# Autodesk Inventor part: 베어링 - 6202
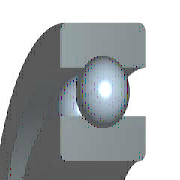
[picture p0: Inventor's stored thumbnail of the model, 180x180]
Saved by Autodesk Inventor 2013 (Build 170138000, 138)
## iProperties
IsCustomPart: 1
Created: 2015-09
Part Number: 베어링 - 6202
Material: 강, 연강
Description: 깊은 그루브 볼 베어링
Document SubType Name: Modeling
Standard: KS B 2023
Designer: mduedu
Standards Organization: KS
Language: ko-KR
Size Designation: 6202 - 15 x 35 x 11
Categories: <MemberInstance><Categories><Category DisplayName="샤프트 부품" InternalName="7f7aeb1f-a693-4053-b835-cee3144e0d98" Mnemonic="SHFT"><Category DisplayName="베어링" Inter
Density: 7.86 g/cm^3
Mass: 45.8725 g
Surface Area: 51.5584 cm^2
Volume: 5.83619 cm^3
Author: mduedu
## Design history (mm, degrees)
sketch "스케치" dims "d0" = 5.2 (= -0.26 x WD + 0.26 x BD)
  geometry: L1 (2.9, 12.5)-(8.1, 12.5); L2 (5.5, 12.5)-(5.5, 9.9); L3 (5.5, 12.5)-(5.5, 15.1); L4 (3.568, 10.76)-(0, 10.76); L5 (0, 7.5)-(11, 7.5); L6 (3.568, 14.24)-(0, 14.24); L7 (0, 17.5)-(11, 17.5); L8 (11, 7.5)-(11, 10.76); L9 (7.432, 10.76)-(11, 10.76); L10 (7.432, 14.24)-(11, 14.24); L11 (11, 17.5)-(11, 14.24); L12 (-1.4, 0)-(8.4, 0) reference; L13 (0, -0.3)-(0, 5.3) reference
  constraints: 22 end point, 4 point on line, 2 collinear, 2 perpendicular, 2 symmetric about line, 1 midpoint, 1 parallel, 14 other
  dimensions: "d9" = 15 diameter of L5 L12 (= WD); "d11" = 35 diameter of L7 L12 (= BD); "d12" = 11 distance between parallel lines of L8 L13 (= KB); "d13" = 21.52 diameter of L9 L12 (= 0.326 x BD + 0.674 x WD)
revolve "본체" stored, may be unused: angle "d6" = 90 deg
revolve "볼" stored, may be unused: angle "d7" = 90 deg
pattern_circular "IDS_ARRAYBALL[SIMPL:T]" dims angle "d3" = 360 deg
body "Solid1"
fillet "모깎기1" dims "d1" = 0.6 (= KRS)
other parameters: "WD" = 15 [user parameter; used in 5 equation terms], "BD" = 35 [user parameter; used in 5 equation terms], "KB" = 11 [user parameter; used in 1 equation term], "KRS" = 0.6 [user parameter; used in 1 equation term], "d4" = 0, "d5" = 0, "d8" = 0, "d14" = 0, "d15" = 0, "BBA" = 0 [user parameter], "BC0" = 3750000 [user parameter], "BC" = 7800000 [user parameter], "BR" = 17.5 (= 0.5 x BD) [user parameter], "WR" = 7.5 (= 0.5 x WD) [user parameter]
